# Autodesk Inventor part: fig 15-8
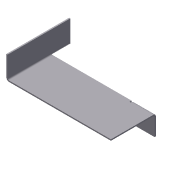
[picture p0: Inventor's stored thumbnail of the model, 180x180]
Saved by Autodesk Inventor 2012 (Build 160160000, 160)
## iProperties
Shininess: 77.0
Angle Display Precision: 2
Document Length Units: 11269
Document Angle Units: 11279
Document Time Units: 11290
Document Mass Units: 11283
Document Length Units Precision: 3
Document Angle Units Precision: 2
Created: 2002-04
Part Number: fig 15-8
Material: Aluminum-6061
Document SubType Name: Sheet Metal
Density: 1 g/cm^3
Sheet Metal Rule: Default
Density: 0.0
Volumn: 0.0
Area: 0.0
PropertySet Name: Model Information
Control State: 0
Master: False
Checked Out: False
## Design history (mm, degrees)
node "Face1"
  sketch "Sketch1"
    geometry: L1 (-49.559, 19.574)-(-49.559, -30.426); L2 (-49.559, -30.426)-(50.441, -30.426); L3 (50.441, -30.426)-(50.441, 19.574); L4 (50.441, 19.574)-(32.941, 19.574); L5 (32.941, 19.574)-(32.941, 4.574); L6 (32.941, 4.574)-(-32.059, 4.574); L7 (-32.059, 4.574)-(-32.059, 19.574); L8 (-32.059, 19.574)-(-49.559, 19.574)
    constraints: 16 end point, 6 parallel, 2 equal length, 1 perpendicular, 1 vertical
    dimensions: "d0" = 100 distance of L1.end L2.end; "d1" = 65 distance of L5.end L6.end; "d2" = 15 distance of L6.end L7.end; "d3" = 50 distance of L1.start L1.end
sketch "Sketch2"
  geometry: L1 (100, 0)-(0, 0) reference; L2 (17.5, 50)-(17.5, 35) reference; L3 (82.5, 50)-(82.5, 0)
  constraints: 2 end point, 1 parallel, 1 point on line
sketch "Sketch3"
  geometry: L1 (81.369, -50)-(0, -50) reference; L2 (17.5, 0)-(17.5, -50)
  constraints: 2 end point, 1 perpendicular, 1 point on line
feature "Fold2" sketch "Sketch3" dims "d8" = 1 (= BendRadius), "d9" = 90 deg, "d10" = 1 (= BendRadius), "d14" = 1 (= BendReliefWidth), "d15" = 0.5 (= BendReliefDepth), "d16" = 2 (= MinimumRemnant), "SeamGap" = 0.01, "Thickness" = 1
sketch "Sketch4"
  geometry: L1 (17.5, 0)-(17.5, -50) reference; L2 (-63.869, -15)-(0, -15) reference; L3 (0, -15)-(17.5, -15)
  constraints: 2 end point, 1 collinear, 1 point on line
feature "Fold3" sketch "Sketch4" dims "d11" = 1 (= BendRadius), "d12" = 90 deg, "d13" = 1 (= BendRadius), "d17" = 1 (= BendReliefWidth), "d18" = 0.5 (= BendReliefDepth), "d19" = 2 (= MinimumRemnant), "SeamGap" = 0.01, "Thickness" = 1
body "Solid1"
face "Plate1" dims "Thickness" = 1
other parameters: "BendRadius" = 1 (= Thickness), "BendReliefWidth" = 1 (= Thickness), "BendReliefDepth" = 0.5 (= 0.5 x Thickness), "CornerReliefSize" = 4 (= 4 x Thickness), "MinimumRemnant" = 2 (= 2 x Thickness), "TransitionRadius" = 1 (= BendRadius), "d4" = 1 (= BendRadius), "JacobiRadiusSize" = 1 (= Thickness), "GapSize" = 1 (= Thickness)
